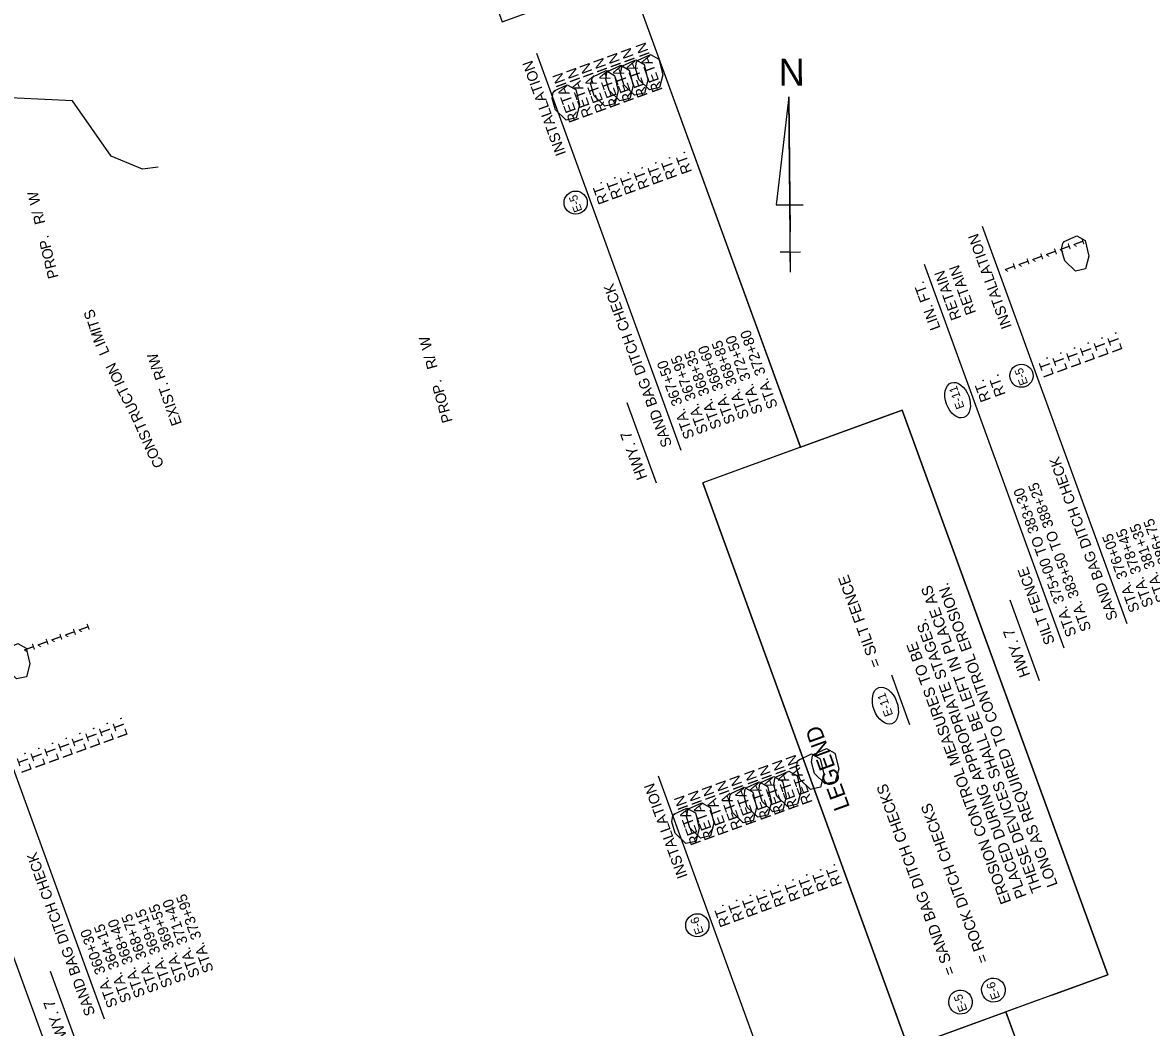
# Model space of a CAD drawing. Extents: x 960650 to 962115, y 1906452 to 1908757.
# Drawn here: x 960982 to 961626, y 1907297 to 1907870 of the extents above; entities that cross this region are included whole.
import ezdxf

# ---------------------------------------------------------------- set-up
doc = ezdxf.new("R2010")
doc.units = 0
for name, color, linetype in [('1', 7, 'Continuous'), ('44', 7, 'Continuous'), ('63', 7, 'Continuous'), ('Level 1', 7, 'Continuous'), ('Level 44', 7, 'Continuous'), ('NO PLOT', 7, 'Continuous'), ('R_Draft', 7, 'Continuous'), ('S_STREAM', 7, 'Continuous'), ('S_TREE', 7, 'Continuous')]:
    doc.layers.add(name, color=color, linetype=linetype)

msp = doc.modelspace()

# ---------------------------------------------------------------- linework, layer by layer
at = {"layer": '1'}
for p, q in [((961425.36, 1907627.47), (961327.48, 1907896.39)), ((961483.4, 1907648.6), (961369.64, 1907607.19)), ((961486.84, 1907285.2), (961369.64, 1907607.19)), ((961568.72, 1907315), (961486.84, 1907285.2)), ((961624.82, 1907079.46), (961542.56, 1907305.48))]:
    msp.add_line(p, q, dxfattribs=at)
msp.add_lwpolyline([(961568.72, 1907315), (961600.59, 1907326.6), (961483.4, 1907648.6)], dxfattribs=at)
for centre in [(961297.13, 1907767), (961551.38, 1907668.27), (961366.53, 1907354.81)]:
    msp.add_circle(centre, 6.61, dxfattribs=at)
msp.add_ellipse((961514.99, 1907654.34), major_axis=(-3.6, 9.89), ratio=0.638788, dxfattribs=at)
at = {"layer": '44'}
for p, q in [((961357.37, 1907625.57), (961274.94, 1907852.04)), ((961611.61, 1907526.84), (961529.18, 1907753.31)), ((961575.72, 1907512.96), (961496.1, 1907731.72)), ((961343.29, 1907606.95), (961326.59, 1907652.84)), ((961561.65, 1907494.34), (961544.94, 1907540.23)), ((961028.38, 1907301.23), (960945.95, 1907527.7)), ((961426.76, 1907213.38), (961344.33, 1907439.85)), ((961014.3, 1907282.61), (960997.6, 1907328.5))]:
    msp.add_line(p, q, dxfattribs=at)
at = {"layer": '63'}
for p, q in [((961418.69, 1907827.3), (961411.58, 1907765.69)), ((961419.63, 1907727.31), (961418.69, 1907827.3)), ((961418.69, 1907827.3), (961419.41, 1907750.38)), ((961411.58, 1907765.69), (961426.96, 1907765.84)), ((961419.63, 1907727.31), (961419.41, 1907750.38)), ((961413.75, 1907738.79), (961425.29, 1907738.9)), ((961419.52, 1907738.84), (961413.75, 1907738.79)), ((961419.63, 1907727.31), (961419.52, 1907738.84))]:
    msp.add_line(p, q, dxfattribs=at)
at = {"layer": 'Level 1'}
for centre, major_axis, ratio in [((961473.76, 1907480.1), (-3.75, 10.3), 0.622952), ((961535.42, 1907317.88), (2.35, -6.47), 0.97521), ((961516.62, 1907311.04), (2.35, -6.47), 0.97521)]:
    msp.add_ellipse(centre, major_axis=major_axis, ratio=ratio, dxfattribs=at)
at = {"layer": 'Level 44'}
msp.add_lwpolyline([(961487.68, 1907469.14), (961477.37, 1907497.45)], dxfattribs=at)
at = {"layer": 'NO PLOT'}
for points in [[(962114.55, 1907257.7), (961568.91, 1908756.85), (961079.18, 1908578.6), (961182.12, 1908295.76), (961245.55, 1908318.85), (961390.91, 1907919.48), (961327.48, 1907896.39), (961425.36, 1907627.47), (961483.4, 1907648.6), (961600.59, 1907326.6), (961542.56, 1907305.48), (961624.82, 1907079.46)], [(962114.55, 1907257.7), (961568.91, 1908756.85), (961079.18, 1908578.6), (961182.12, 1908295.76), (961245.55, 1908318.85), (961390.91, 1907919.48), (961327.48, 1907896.39), (961425.36, 1907627.47), (961483.4, 1907648.6), (961600.59, 1907326.6), (961542.56, 1907305.48), (961624.82, 1907079.46)], [(962114.55, 1907257.7), (961568.91, 1908756.85), (961079.18, 1908578.6), (961182.12, 1908295.76), (961245.55, 1908318.85), (961390.91, 1907919.48), (961327.48, 1907896.39), (961425.36, 1907627.47), (961483.4, 1907648.6), (961600.59, 1907326.6), (961542.56, 1907305.48), (961624.82, 1907079.46)], [(962114.55, 1907257.7), (961568.91, 1908756.85), (961079.18, 1908578.6), (961182.12, 1908295.76), (961245.55, 1908318.85), (961390.91, 1907919.48), (961327.48, 1907896.39), (961425.36, 1907627.47), (961483.4, 1907648.6), (961600.59, 1907326.6), (961542.56, 1907305.48), (961624.82, 1907079.46)], [(962114.55, 1907257.7), (961568.91, 1908756.85), (961079.18, 1908578.6), (961182.12, 1908295.76), (961245.55, 1908318.85), (961390.91, 1907919.48), (961327.48, 1907896.39), (961425.36, 1907627.47), (961483.4, 1907648.6), (961600.59, 1907326.6), (961542.56, 1907305.48), (961624.82, 1907079.46)], [(961135.09, 1906901.21), (960730.12, 1908013.86), (960776.54, 1908030.76), (960709.57, 1908214.75), (960723.29, 1908219.74), (960649.59, 1908422.25), (961079.18, 1908578.6), (961182.12, 1908295.76), (961109.77, 1908269.43), (961255.13, 1907870.06), (961327.48, 1907896.39), (961425.36, 1907627.47), (961369.64, 1907607.19), (961486.84, 1907285.2), (961542.56, 1907305.48), (961624.82, 1907079.46)], [(961135.09, 1906901.21), (960730.12, 1908013.86), (960776.54, 1908030.76), (960709.57, 1908214.75), (960723.29, 1908219.74), (960649.59, 1908422.25), (961079.18, 1908578.6), (961182.12, 1908295.76), (961109.77, 1908269.43), (961255.13, 1907870.06), (961327.48, 1907896.39), (961425.36, 1907627.47), (961369.64, 1907607.19), (961486.84, 1907285.2), (961542.56, 1907305.48), (961624.82, 1907079.46)], [(961135.09, 1906901.21), (960730.12, 1908013.86), (960776.54, 1908030.76), (960709.57, 1908214.75), (960723.29, 1908219.74), (960649.59, 1908422.25), (961079.18, 1908578.6), (961182.12, 1908295.76), (961109.77, 1908269.43), (961255.13, 1907870.06), (961327.48, 1907896.39), (961425.36, 1907627.47), (961369.64, 1907607.19), (961486.84, 1907285.2), (961542.56, 1907305.48), (961624.82, 1907079.46)], [(961135.09, 1906901.21), (960730.12, 1908013.86), (960776.54, 1908030.76), (960709.57, 1908214.75), (960723.29, 1908219.74), (960649.59, 1908422.25), (961079.18, 1908578.6), (961182.12, 1908295.76), (961109.77, 1908269.43), (961255.13, 1907870.06), (961327.48, 1907896.39), (961425.36, 1907627.47), (961369.64, 1907607.19), (961486.84, 1907285.2), (961542.56, 1907305.48), (961624.82, 1907079.46)], [(961135.09, 1906901.21), (960730.12, 1908013.86), (960776.54, 1908030.76), (960709.57, 1908214.75), (960723.29, 1908219.74), (960649.59, 1908422.25), (961079.18, 1908578.6), (961182.12, 1908295.76), (961109.77, 1908269.43), (961255.13, 1907870.06), (961327.48, 1907896.39), (961425.36, 1907627.47), (961369.64, 1907607.19), (961486.84, 1907285.2), (961542.56, 1907305.48), (961624.82, 1907079.46)]]:
    msp.add_lwpolyline(points, close=True, dxfattribs=at)
at = {"layer": 'S_STREAM'}
msp.add_lwpolyline([(961059, 1907787.27), (961049.99, 1907786.16), (961032.27, 1907793.42), (961021.24, 1907809.22), (961010.21, 1907825.01), (960994.4, 1907825.81), (960978.59, 1907826.61), (960962.78, 1907827.4), (960946.97, 1907828.2), (960933.72, 1907835.05), (960920.48, 1907841.89), (960921.55, 1907866.06), (960922.63, 1907890.23), (960900.34, 1907892.36), (960878.06, 1907894.49), (960855.77, 1907896.62), (960833.49, 1907898.75)], dxfattribs=at)
at = {"layer": 'S_TREE'}
for points in [[(961332.35, 1907848.04), (961339.82, 1907851.52), (961344.65, 1907848.79), (961346.8, 1907839.96), (961344.86, 1907832.58), (961339.16, 1907831.31), (961333.08, 1907837.19), (961331.22, 1907843.64), (961331.84, 1907847.29), (961333.03, 1907848.51)], [(961332.35, 1907848.04), (961339.82, 1907851.52), (961344.65, 1907848.79), (961346.8, 1907839.96), (961344.86, 1907832.58), (961339.16, 1907831.31), (961333.08, 1907837.19), (961331.22, 1907843.64), (961331.84, 1907847.29), (961333.03, 1907848.51)], [(961315.43, 1907841.88), (961322.91, 1907845.37), (961327.73, 1907842.63), (961329.88, 1907833.8), (961327.95, 1907826.42), (961322.25, 1907825.15), (961316.17, 1907831.03), (961314.31, 1907837.48), (961314.92, 1907841.13), (961316.11, 1907842.36)], [(961323.89, 1907844.96), (961331.36, 1907848.44), (961336.19, 1907845.71), (961338.34, 1907836.88), (961336.41, 1907829.5), (961330.7, 1907828.23), (961324.62, 1907834.11), (961322.77, 1907840.56), (961323.38, 1907844.21), (961324.57, 1907845.43)], [(961323.89, 1907844.96), (961331.36, 1907848.44), (961336.19, 1907845.71), (961338.34, 1907836.88), (961336.41, 1907829.5), (961330.7, 1907828.23), (961324.62, 1907834.11), (961322.77, 1907840.56), (961323.38, 1907844.21), (961324.57, 1907845.43)], [(961323.89, 1907844.96), (961331.36, 1907848.44), (961336.19, 1907845.71), (961338.34, 1907836.88), (961336.41, 1907829.5), (961330.7, 1907828.23), (961324.62, 1907834.11), (961322.77, 1907840.56), (961323.38, 1907844.21), (961324.57, 1907845.43)], [(961306.97, 1907838.8), (961314.45, 1907842.29), (961319.28, 1907839.55), (961321.43, 1907830.73), (961319.49, 1907823.34), (961313.79, 1907822.07), (961307.71, 1907827.96), (961305.85, 1907834.4), (961306.46, 1907838.06), (961307.66, 1907839.28)], [(961306.97, 1907838.8), (961314.45, 1907842.29), (961319.28, 1907839.55), (961321.43, 1907830.73), (961319.49, 1907823.34), (961313.79, 1907822.07), (961307.71, 1907827.96), (961305.85, 1907834.4), (961306.46, 1907838.06), (961307.66, 1907839.28)], [(961284.9, 1907830.77), (961292.37, 1907834.25), (961297.2, 1907831.52), (961299.35, 1907822.69), (961297.41, 1907815.31), (961291.71, 1907814.04), (961285.63, 1907819.92), (961283.77, 1907826.37), (961284.38, 1907830.02), (961285.58, 1907831.24)], [(961575.45, 1907744.62), (961582.92, 1907748.1), (961587.75, 1907745.37), (961589.9, 1907736.54), (961587.96, 1907729.16), (961582.26, 1907727.89), (961576.18, 1907733.77), (961574.32, 1907740.22), (961574.93, 1907743.87), (961576.13, 1907745.09)], [(960971.41, 1907512.07), (960978.89, 1907515.56), (960983.71, 1907512.82), (960985.86, 1907503.99), (960983.93, 1907496.61), (960978.23, 1907495.34), (960972.15, 1907501.22), (960970.29, 1907507.67), (960970.9, 1907511.32), (960972.09, 1907512.54)], [(961424.24, 1907449.09), (961431.72, 1907452.58), (961436.54, 1907449.84), (961438.69, 1907441.02), (961436.76, 1907433.63), (961431.06, 1907432.36), (961424.98, 1907438.25), (961423.12, 1907444.69), (961423.73, 1907448.35), (961424.92, 1907449.57)], [(961424.24, 1907449.09), (961431.72, 1907452.58), (961436.54, 1907449.84), (961438.69, 1907441.02), (961436.76, 1907433.63), (961431.06, 1907432.36), (961424.98, 1907438.25), (961423.12, 1907444.69), (961423.73, 1907448.35), (961424.92, 1907449.57)], [(961432.7, 1907452.17), (961440.17, 1907455.66), (961445, 1907452.92), (961447.15, 1907444.09), (961445.22, 1907436.71), (961439.51, 1907435.44), (961433.43, 1907441.32), (961431.58, 1907447.77), (961432.19, 1907451.43), (961433.38, 1907452.65)], [(961432.7, 1907452.17), (961440.17, 1907455.66), (961445, 1907452.92), (961447.15, 1907444.09), (961445.22, 1907436.71), (961439.51, 1907435.44), (961433.43, 1907441.32), (961431.58, 1907447.77), (961432.19, 1907451.43), (961433.38, 1907452.65)], [(961432.7, 1907452.17), (961440.17, 1907455.66), (961445, 1907452.92), (961447.15, 1907444.09), (961445.22, 1907436.71), (961439.51, 1907435.44), (961433.43, 1907441.32), (961431.58, 1907447.77), (961432.19, 1907451.43), (961433.38, 1907452.65)], [(961402.74, 1907436.21), (961410.22, 1907439.7), (961415.05, 1907436.97), (961417.2, 1907428.14), (961415.26, 1907420.76), (961409.56, 1907419.48), (961403.48, 1907425.37), (961401.62, 1907431.81), (961402.23, 1907435.47), (961403.43, 1907436.69)], [(961402.74, 1907436.21), (961410.22, 1907439.7), (961415.05, 1907436.97), (961417.2, 1907428.14), (961415.26, 1907420.76), (961409.56, 1907419.48), (961403.48, 1907425.37), (961401.62, 1907431.81), (961402.23, 1907435.47), (961403.43, 1907436.69)], [(961411.2, 1907439.29), (961418.67, 1907442.78), (961423.5, 1907440.05), (961425.65, 1907431.22), (961423.72, 1907423.84), (961418.01, 1907422.56), (961411.94, 1907428.45), (961410.08, 1907434.89), (961410.69, 1907438.55), (961411.88, 1907439.77)], [(961411.2, 1907439.29), (961418.67, 1907442.78), (961423.5, 1907440.05), (961425.65, 1907431.22), (961423.72, 1907423.84), (961418.01, 1907422.56), (961411.94, 1907428.45), (961410.08, 1907434.89), (961410.69, 1907438.55), (961411.88, 1907439.77)], [(961385.83, 1907430.06), (961393.3, 1907433.54), (961398.13, 1907430.81), (961400.28, 1907421.98), (961398.35, 1907414.6), (961392.64, 1907413.33), (961386.56, 1907419.21), (961384.71, 1907425.66), (961385.32, 1907429.31), (961386.51, 1907430.53)], [(961394.29, 1907433.14), (961401.76, 1907436.62), (961406.59, 1907433.89), (961408.74, 1907425.06), (961406.8, 1907417.68), (961401.1, 1907416.41), (961395.02, 1907422.29), (961393.16, 1907428.74), (961393.78, 1907432.39), (961394.97, 1907433.61)], [(961353.11, 1907418.15), (961360.58, 1907421.64), (961365.41, 1907418.9), (961367.56, 1907410.07), (961365.63, 1907402.69), (961359.92, 1907401.42), (961353.84, 1907407.3), (961351.99, 1907413.75), (961352.6, 1907417.4), (961353.79, 1907418.63)], [(961353.11, 1907418.15), (961360.58, 1907421.64), (961365.41, 1907418.9), (961367.56, 1907410.07), (961365.63, 1907402.69), (961359.92, 1907401.42), (961353.84, 1907407.3), (961351.99, 1907413.75), (961352.6, 1907417.4), (961353.79, 1907418.63)], [(961353.11, 1907418.15), (961360.58, 1907421.64), (961365.41, 1907418.9), (961367.56, 1907410.07), (961365.63, 1907402.69), (961359.92, 1907401.42), (961353.84, 1907407.3), (961351.99, 1907413.75), (961352.6, 1907417.4), (961353.79, 1907418.63)], [(961361.57, 1907421.23), (961369.04, 1907424.71), (961373.87, 1907421.98), (961376.02, 1907413.15), (961374.08, 1907405.77), (961368.38, 1907404.5), (961362.3, 1907410.38), (961360.44, 1907416.83), (961361.06, 1907420.48), (961362.25, 1907421.7)], [(961361.57, 1907421.23), (961369.04, 1907424.71), (961373.87, 1907421.98), (961376.02, 1907413.15), (961374.08, 1907405.77), (961368.38, 1907404.5), (961362.3, 1907410.38), (961360.44, 1907416.83), (961361.06, 1907420.48), (961362.25, 1907421.7)]]:
    msp.add_lwpolyline(points, dxfattribs=at)

# ---------------------------------------------------------------- texts
at = {"layer": '1'}
for s, rotation, p in [('E-5 ', 110, (961300.98, 1907762.54)), ('E-5 ', 110, (961555.22, 1907663.81)), ('E-11', 109.99998, (961518.98, 1907650.27)), ('E-6 ', 110, (961370.27, 1907350.64))]:
    msp.add_text(s, height=4.8, rotation=rotation, dxfattribs=at).set_placement(p)
at = {"layer": '44'}
for s, height, rotation, p in [('RETAIN', 6, 110, (961346.79, 1907831.31)), ('RETAIN', 6, 110, (961330.5, 1907825.38)), ('RETAIN', 6, 110, (961338.33, 1907828.23)), ('INSTALLATION', 6, 110, (961291.71, 1907794.98)), ('RETAIN', 6, 110, (961314.84, 1907819.68)), ('RETAIN', 6, 110, (961322.67, 1907822.53)), ('RETAIN', 6, 110, (961299.34, 1907814.04)), ('RETAIN', 6, 110, (961307.17, 1907816.89)), ('RT.', 6, 110, (961363.6, 1907784.65)), ('RT.', 6, 110, (961339.48, 1907775.88)), ('RT.', 6, 110, (961347.31, 1907778.73)), ('RT.', 6, 110, (961355.14, 1907781.58)), ('RT.', 6, 110, (961323.97, 1907770.23)), ('RT.', 6, 110, (961331.65, 1907773.03)), ('RT.', 6, 110, (961316.14, 1907767.38)), ('INSTALLATION', 6, 110, (961545.95, 1907696.25)), ('1', 6, 110, (961579.72, 1907739.99)), ('1', 6, 110, (961587.55, 1907742.84)), ('1', 6, 110, (961556.23, 1907731.44)), ('1', 6, 110, (961564.06, 1907734.29)), ('1', 6, 110, (961571.89, 1907737.14)), ('RETAIN', 6, 109.99998, (961525.62, 1907704.32)), ('1', 6, 110, (961548.4, 1907728.59)), ('RETAIN', 6, 109.99998, (961517.21, 1907701.26)), ('SAND BAG DITCH CHECK', 6, 110, (961352.2, 1907628.79)), ('LIN. FT.', 6, 109.99998, (961505.27, 1907695.53)), ('STA. 372+50', 6, 110, (961404.04, 1907647.65)), ('STA. 372+80', 6, 110, (961412.5, 1907650.73)), ('LT.', 6, 110, (961601.35, 1907680.08)), ('LT.', 6, 110, (961609.18, 1907682.93)), ('STA. 368+60', 6, 110, (961388.38, 1907641.95)), ('STA. 368+85', 6, 110, (961396.21, 1907644.8)), ('LT.', 6, 110, (961585.69, 1907674.38)), ('LT.', 6, 110, (961593.52, 1907677.23)), ('STA. 367+95', 6, 110, (961372.87, 1907636.31)), ('STA. 368+35', 6, 110, (961380.55, 1907639.1)), ('LT.', 6, 110, (961570.03, 1907668.68)), ('LT.', 6, 110, (961577.86, 1907671.53)), ('STA. 367+50', 6, 110, (961365.04, 1907633.46)), ('RT.', 6, 109.99998, (961534.02, 1907654.6)), ('RT.', 6, 109.99998, (961542.43, 1907657.66)), ('HWY. 7', 6.25, 110, (961338.08, 1907610.2)), ('SAND BAG DITCH CHECK', 6, 110, (961606.44, 1907530.06)), ('STA. 383+50 TO 388+25', 6, 109.99998, (961591.33, 1907523.74)), ('STA. 375+00 TO 383+30', 6, 109.99998, (961582.92, 1907520.68)), ('STA. 378+45', 6, 110, (961626.81, 1907537.47)), ('STA. 381+35', 6, 110, (961634.64, 1907540.32)), ('STA. 386+75', 6, 110, (961642.47, 1907543.17)), ('STA. 376+05', 6, 110, (961618.98, 1907534.62)), ('SILT FENCE      ', 6, 109.99998, (961570.55, 1907516.18)), ('1', 6, 110, (961012.35, 1907520.14)), ('1', 6, 110, (961020.17, 1907522.99)), ('1', 6, 110, (960996.76, 1907514.47)), ('1', 6, 110, (961004.59, 1907517.32)), ('HWY. 7', 6.25, 110, (961556.44, 1907497.6)), ('1', 6, 110, (960988.97, 1907511.64)), ('LT.', 6, 110, (961041.8, 1907463.08)), ('LT.', 6, 110, (961026.22, 1907457.41)), ('LT.', 6, 110, (961033.97, 1907460.23)), ('LT.', 6, 110, (961002.77, 1907448.88)), ('LT.', 6, 110, (961010.6, 1907451.73)), ('LT.', 6, 110, (961018.39, 1907454.56)), ('LT.', 6, 110, (960987.11, 1907443.18)), ('LT.', 6, 110, (960994.94, 1907446.03)), ('RETAIN', 6, 110, (961432.37, 1907425.01)), ('RETAIN', 6, 110, (961416.63, 1907419.29)), ('RETAIN', 6, 110, (961424.54, 1907422.17)), ('RETAIN', 6, 110, (961400.27, 1907413.33)), ('RETAIN', 6, 110, (961408.73, 1907416.41)), ('INSTALLATION', 6, 110, (961361.11, 1907382.79)), ('RETAIN', 6, 110, (961384.47, 1907407.58)), ('RETAIN', 6, 110, (961392.37, 1907410.46)), ('RETAIN', 6, 110, (961368.74, 1907401.86)), ('RETAIN', 6, 110, (961376.64, 1907404.73)), ('SAND BAG DITCH CHECK', 6, 110, (961023.21, 1907304.45)), ('RT.', 6, 110, (961449.17, 1907378.36)), ('RT.', 6, 110, (961425.54, 1907369.75)), ('RT.', 6, 110, (961433.44, 1907372.63)), ('RT.', 6, 110, (961441.34, 1907375.51)), ('RT.', 6, 110, (961409.18, 1907363.8)), ('RT.', 6, 110, (961417.08, 1907366.68)), ('STA. 371+40', 6, 110, (961082.92, 1907326.18)), ('STA. 373+95', 6, 110, (961090.75, 1907329.03)), ('RT.', 6, 110, (961393.44, 1907358.07)), ('RT.', 6, 110, (961401.27, 1907360.92)), ('STA. 369+15', 6, 110, (961067.34, 1907320.51)), ('STA. 369+55', 6, 110, (961075.17, 1907323.36)), ('RT.', 6, 110, (961385.54, 1907355.2)), ('STA. 364+15', 6, 110, (961043.89, 1907311.97)), ('STA. 368+40', 6, 110, (961051.72, 1907314.82)), ('STA. 368+75', 6, 110, (961059.54, 1907317.67)), ('STA. 360+30', 6, 110, (961036.06, 1907309.12)), ('HWY. 7', 6.25, 110, (961009.09, 1907285.86))]:
    msp.add_text(s, height=height, rotation=rotation, dxfattribs=at).set_placement(p)
at = {"layer": '63'}
msp.add_text('N', height=15.38, rotation=0.53522, dxfattribs=at).set_placement((961413, 1907833.66))
at = {"layer": 'Level 1'}
for s, height, p in [('= SILT FENCE', 6.25, (961471.51, 1907503.16)), ('THESE DEVICES SHALL BE LEFT IN PLACE AS ', 6.25, (961563.34, 1907374.73)), ('LONG AS REQUIRED TO CONTROL EROSION.', 6.25, (961572.18, 1907377.95)), ('PLACED DURING APPROPRIATE STAGES. ', 6.25, (961554.5, 1907371.51)), ('EROSION CONTROL MEASURES TO BE', 6.25, (961545.65, 1907368.29)), ('E-11 ', 4.876, (961478.2, 1907474.92)), ('= SAND BAG DITCH CHECKS', 6.25, (961513.91, 1907327.64)), ('= ROCK DITCH CHECKS', 6.25, (961532.7, 1907334.48)), ('E-6 ', 4.876, (961539.27, 1907313.52)), ('E-5 ', 4.876, (961520.64, 1907306.5))]:
    msp.add_text(s, height=height, rotation=110.00001, dxfattribs=at).set_placement(p)
at = {"layer": 'Level 44'}
msp.add_text('LEGEND', height=9.143, rotation=110.00001, dxfattribs=at).set_placement((961453.67, 1907422.25))
at = {"layer": 'R_Draft'}
for s, rotation, p in [('W', 103.74761, (960991.92, 1907766.58)), ('/', 103.74761, (960993.31, 1907760.89)), ('R', 103.74761, (960994.66, 1907755.39)), ('.', 103.74761, (960996.78, 1907746.71)), ('P', 103.74761, (960998.13, 1907741.21)), ('O', 103.74761, (960999.52, 1907735.51)), ('R', 103.74761, (961000.87, 1907730.01)), ('P', 103.74761, (961002.22, 1907724.5)), ('S', 111.59731, (961023.8, 1907701.78)), ('T', 107.50401, (961025.73, 1907696.25)), ('I', 107.50401, (961026.33, 1907694.36)), ('M', 107.50401, (961028.26, 1907688.23)), ('I', 113.80825, (961029.24, 1907686.48)), ('L', 113.80825, (961031.41, 1907681.56)), ('W', 105.56378, (961215.38, 1907684.09)), ('EXIST. R/W', 109.46478, (961072.59, 1907641.04)), ('/', 105.56378, (961216.96, 1907678.45)), ('R', 105.56378, (961218.48, 1907672.99)), ('N', 117.95791, (961036.82, 1907671.22)), ('O', 115.13257, (961039.28, 1907665.9)), ('I', 115.13257, (961040.12, 1907664.1)), ('.', 105.56378, (961220.87, 1907664.39)), ('T', 117.01435, (961042.73, 1907658.86)), ('C', 117.01435, (961045.31, 1907653.81)), ('P', 105.56378, (961222.39, 1907658.92)), ('O', 105.56378, (961223.97, 1907653.28)), ('U', 117.63976, (961047.98, 1907648.7)), ('R', 105.56378, (961225.49, 1907647.82)), ('R', 117.63976, (961050.61, 1907643.68)), ('P', 105.56378, (961227.01, 1907642.36)), ('T', 113.17383, (961052.84, 1907638.26)), ('S', 113.17383, (961055.07, 1907633.05)), ('N', 113.89291, (961057.4, 1907627.88)), ('O', 117.71051, (961060.02, 1907622.64)), ('C', 117.71051, (961062.65, 1907617.62))]:
    msp.add_text(s, height=6, rotation=rotation, dxfattribs=at).set_placement(p)

doc.saveas('drawing.dxf')
